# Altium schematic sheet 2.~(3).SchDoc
size 420 x 297 mm
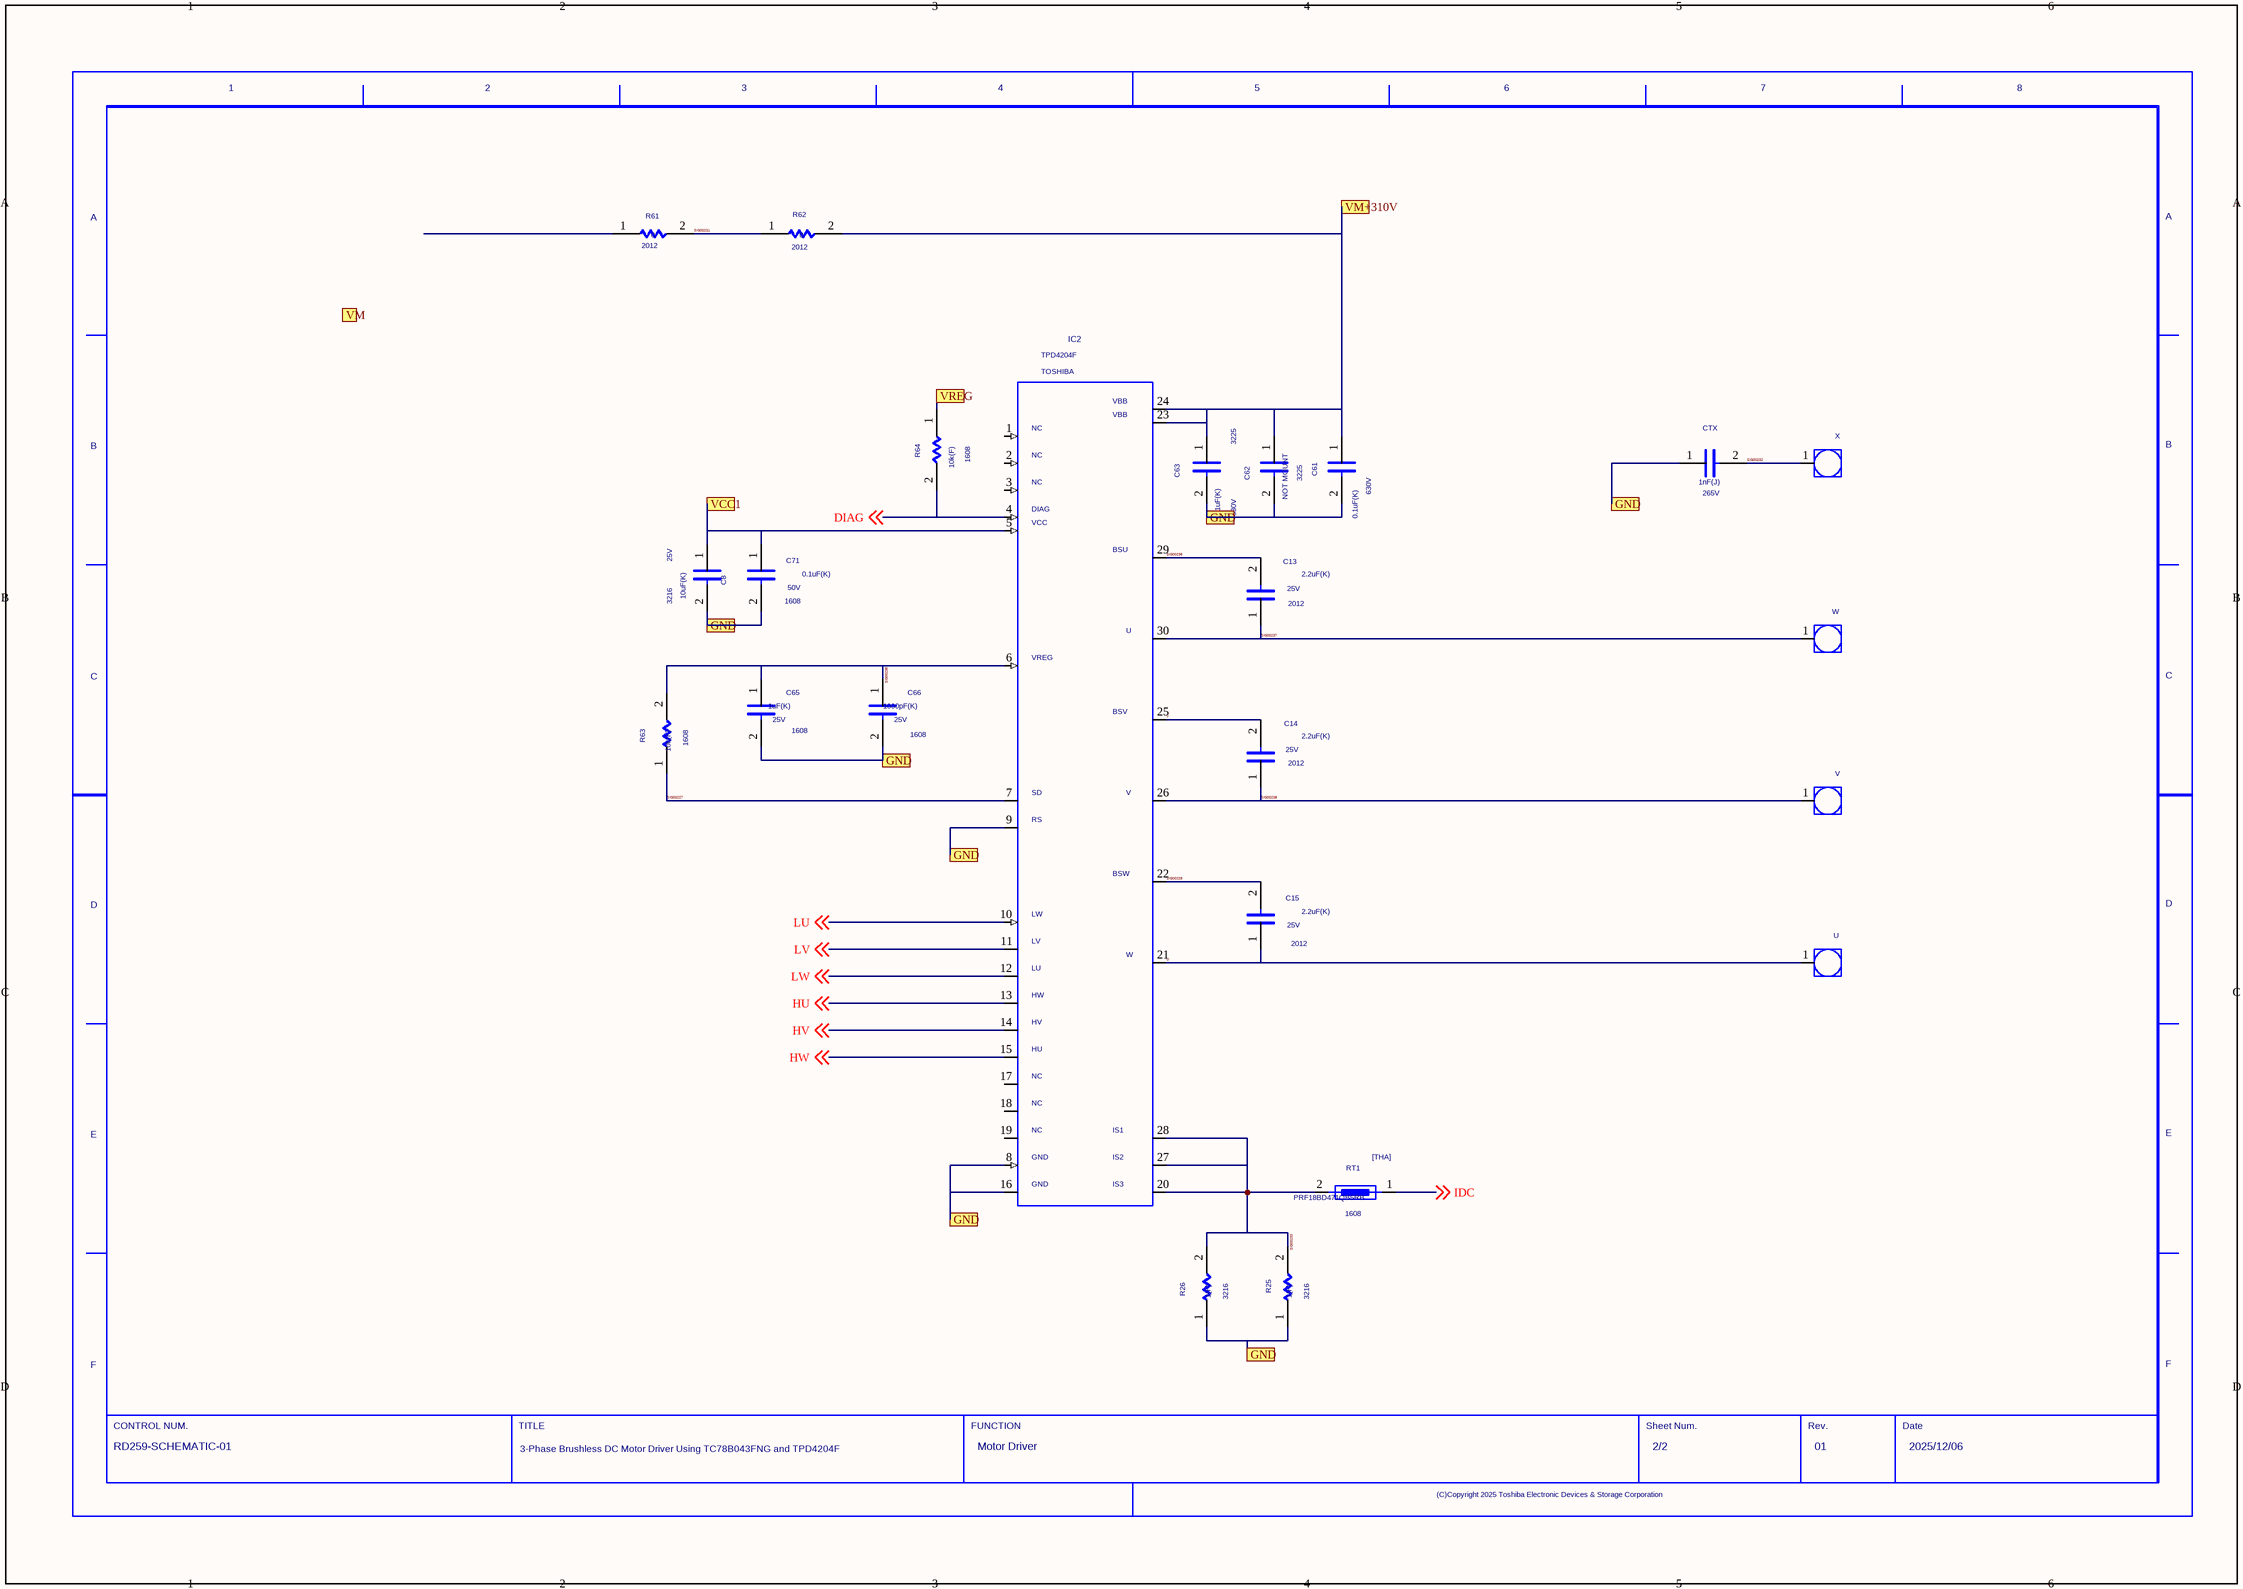
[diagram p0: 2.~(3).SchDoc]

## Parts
C8  VAL1: 10uF(K)  VAL2: 25V  SIZECODESMD: 3216  (hidden comment: C)
C13  VAL1: 2.2uF(K)  VAL2: 25V  SIZECODESMD: 2012  (hidden comment: C)
C14  VAL1: 2.2uF(K)  VAL2: 25V  SIZECODESMD: 2012  (hidden comment: C)
C15  VAL1: 2.2uF(K)  VAL2: 25V  SIZECODESMD: 2012  (hidden comment: C)
C61  VAL1: 0.1uF(K)  VAL2: 630V  (hidden comment: C)
C62  SIZECODESMD: 3225  NOTMNT: NOT MOUNT  (hidden comment: C)
C63  VAL1: 0.1uF(K)  VAL2: 630V  SIZECODESMD: 3225  (hidden comment: C)
C65  VAL1: 1uF(K)  VAL2: 25V  SIZECODESMD: 1608  (hidden comment: C)
C66  VAL1: 1000pF(K)  VAL2: 25V  SIZECODESMD: 1608  (hidden comment: C)
C71  VAL1: 0.1uF(K)  VAL2: 50V  SIZECODESMD: 1608  (hidden comment: C)
CTX  VAL1: 1nF(J)  VAL2: 265V  (hidden comment: C)
IC2  USERCOMPTEXT3: TOSHIBA  (hidden comment: TPD4204F)
R25  VAL1: 1(F)  SIZECODESMD: 3216  (hidden comment: R)
R26  VAL1: 1(F)  SIZECODESMD: 3216  (hidden comment: R)
R61  VAL1: 0  SIZECODESMD: 2012  (hidden comment: R)
R62  VAL1: 0  SIZECODESMD: 2012  (hidden comment: R)
R63  VAL1: 10k(F)  SIZECODESMD: 1608  (hidden comment: R)
R64  VAL1: 10k(F)  SIZECODESMD: 1608  (hidden comment: R)
RT1  SIZECODESMD: 1608  VAL3: PRF18BD471QB5RB  (hidden comment: THA)
U  PAD_FOR_BLDCS50  (value not drawn)
U?  DATE: 2025/12/06  DRAWINGNUMBER: RD259-SCHEMATIC-01  TITLE: 3-Phase Brushless DC Motor Driver / Using TC78B043FNG and TPD4204F  FUNCTION: Motor Driver  SHEETNUMBER: 2/2  REVISION: 01  (hidden comment: WAKU_DEF100)
V  PAD_FOR_BLDCS50  (value not drawn)
W  PAD_FOR_BLDCS50  (value not drawn)
X  PAD_FOR_BLDCS50  (value not drawn)

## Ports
GND, VCC1, VM, VM+310V, VREG

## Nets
DIAG: IC2.4 R64.2 ; off-sheet DIAG
GND: C8.2 C61.2 C62.2 C63.2 C65.2 C66.2 C71.2 CTX.1 IC2.8 IC2.9 IC2.16 R25.1 R26.1 ; port GND
HU: IC2.13 ; off-sheet HU
HV: IC2.14 ; off-sheet HV
HW: IC2.15 ; off-sheet HW
IDC: RT1.1 ; off-sheet IDC
LU: IC2.10 ; off-sheet LU
LV: IC2.11 ; off-sheet LV
LW: IC2.12 ; off-sheet LW
SIG00227: IC2.7 R63.1
SIG00228: C15.2 IC2.22
SIG00231: R61.2 R62.1
SIG00232: CTX.2 X.1
SIG00233: IC2.20 IC2.27 IC2.28 R25.2 R26.2 RT1.2
SIG00235: C65.1 C66.1 IC2.6 R63.2
SIG00236: C13.2 IC2.29
SIG00237: C13.1 IC2.30 W.1
SIG00238: C14.1 IC2.26 V.1
U: C15.1 IC2.21 U.1
V: C14.2 IC2.25
VCC1: C8.1 C71.1 IC2.5 ; port VCC1
VM+310V: C61.1 C62.1 C63.1 IC2.23 IC2.24 R62.2 ; port VM+310V
VREG: R64.1 ; port VREG

Not connected (* = marked no-connect by the designer): IC2 1 2 3 17 18 19; R61 1

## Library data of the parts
C8 C61 C65 C66 C71 CTX = C_Dup1: OriginalSymbolOrigin: (2540,7620); SAVECOUNT: 0
C13-C15 = C_Dup1: OriginalSymbolOrigin: (2540,7620); NOTMNT: MOUNT; USEWITHLAYOUT: YES; SAVECOUNT: 0
C62 = C: OriginalSymbolOrigin: (2540,7620); SAVECOUNT: 0
C63 = C_Dup1: OriginalSymbolOrigin: (2540,7620); USEWITHLAYOUT: YES; SAVECOUNT: 0
IC2 = TPD4204F: TIME: 16:32:01; UPDATEUSER: t5459927; UPDATETIME: 11:42:20; SAVECOUNT: 10; SAVEAREA0: -38352,-57023,57455,-16941; OriginalSymbolOrigin: (2540,154940)
R25 R26 = R_Dup1: VAL2: 500mW; OriginalSymbolOrigin: (5080,5080); SAVECOUNT: 0
R61 R62 = R_Dup1: OriginalSymbolOrigin: (5080,5080)
R63 = R_Dup1: VAL2: 100mW; OriginalSymbolOrigin: (5080,5080); SAVECOUNT: 0
R64 = R: VAL2: 100mW; OriginalSymbolOrigin: (5080,5080); SAVECOUNT: 0
RT1 = THA: SAVECOUNT: 3; SAVEAREA0: -562,-143,15615,10489; TIME: 16:37:29; UPDATEUSER: sato-yr; OriginalSymbolOrigin: (2540,5080)
U V W X = PAD_FOR_BLDCS50: SAVEAREA0: -12224,-318,37706,25614; TIME: 11:47:14; UPDATEUSER: t5459927; UPDATETIME: 16:31:56; SAVECOUNT: 8; OriginalSymbolOrigin: (7620,17780); DEVICE: PAD
U? = WAKU_DEF100: SAVEAREA0: -63393,-16950,474261,314592; TIME: 14:30:25; UPDATEUSER: t5459927; UPDATETIME: 15:25:20; SAVECOUNT: 3; OriginalSymbolOrigin: (10160,284480)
